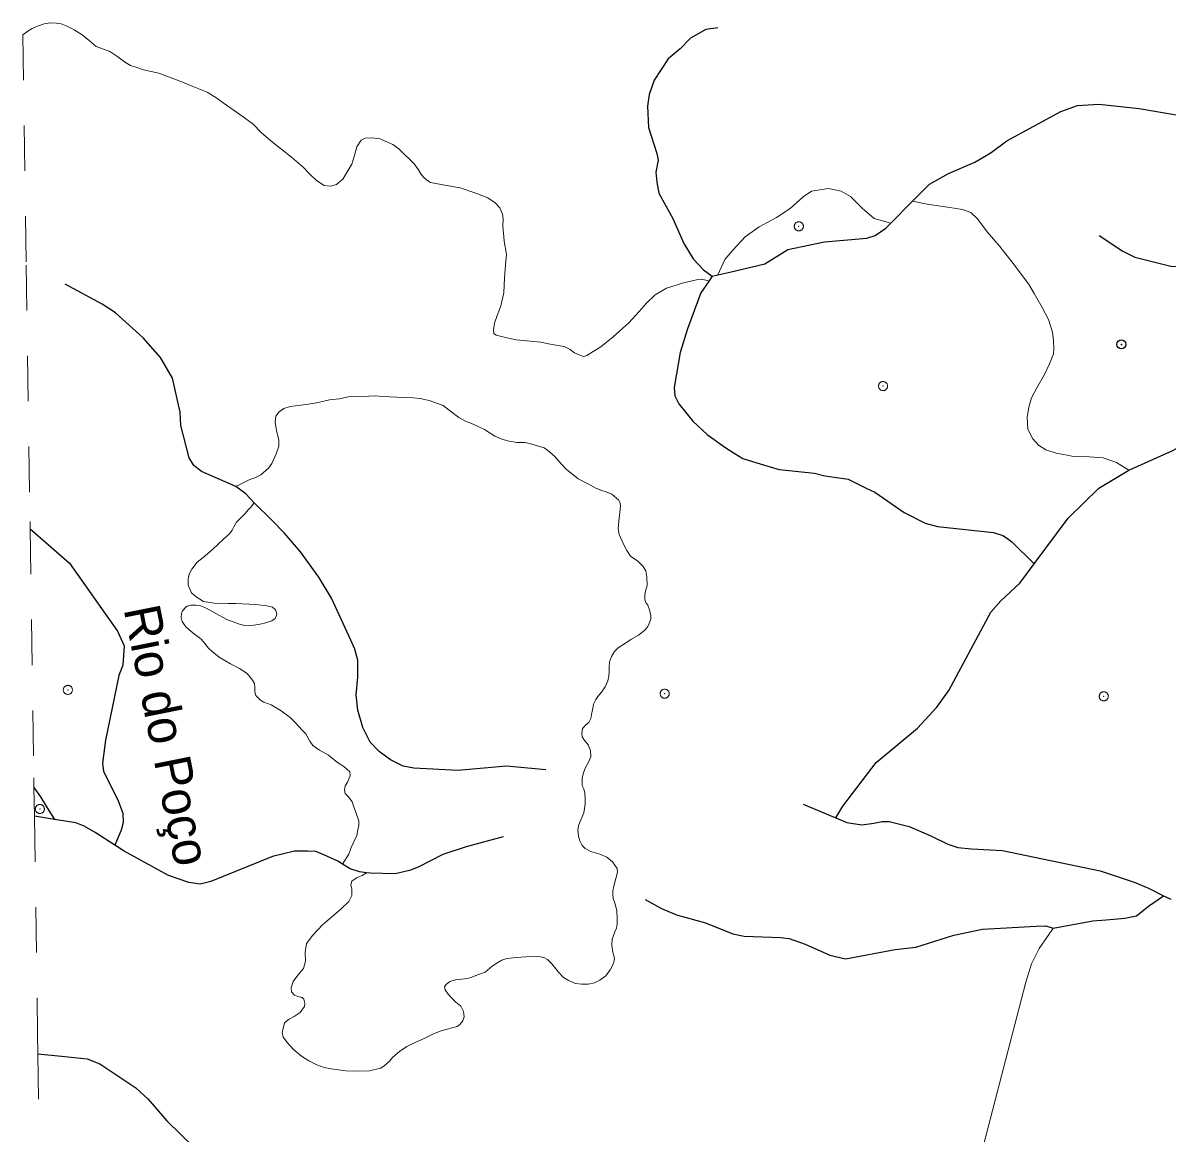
# Model space of a CAD drawing. Extents: x 267.7 to 296, y 7537.7 to 7565.8.
# Drawn here: x 267.776 to 270.298, y 7557.869 to 7560.316 of the extents above; entities that cross this region are included whole.
import ezdxf
from ezdxf.enums import TextEntityAlignment as Align

# ---------------------------------------------------------------- set-up
doc = ezdxf.new("R2010")
doc.units = 0
doc.header["$LTSCALE"] = 0.04
doc.header["$PDMODE"] = 32
doc.header["$PDSIZE"] = 0.02
doc.linetypes.add('SHORT_DASHED', pattern=[2.7, 1.5, -1.2])
for name, color, linetype, lineweight in [('1', 7, 'Continuous', 25), ('21', 7, 'SHORT_DASHED', 13), ('62', 7, 'SHORT_DASHED', 13), ('7', 7, 'Continuous', 25)]:
    doc.layers.add(name, color=color, linetype=linetype, lineweight=lineweight)
doc.layers.add('54', color=7, linetype='Continuous')
doc.layers.add('61', color=7, linetype='Continuous')

msp = doc.modelspace()

# ---------------------------------------------------------------- linework, layer by layer
at = {"layer": '1', "lineweight": 13}
msp.add_lwpolyline([(269.4313, 7557.2767), (269.5283, 7557.3725), (269.8469, 7557.6964), (269.8574, 7557.7104), (269.8653, 7557.7332), (269.8985, 7557.8627), (269.987, 7558.2015), (269.9992, 7558.2418), (270.0158, 7558.2759), (270.0342, 7558.3022), (270.0471, 7558.3206)], dxfattribs=at)
at = {"layer": '21'}
for points in [[(267.7967, 7560.3032), (267.7872, 7560.2972), (267.776, 7560.2894)], [(267.8606, 7560.3133), (267.8499, 7560.3151), (267.8361, 7560.3157), (267.823, 7560.3133), (267.8081, 7560.3085), (267.7967, 7560.3032)], [(269.2885, 7559.7474), (269.2712, 7559.7508), (269.261, 7559.7496), (269.2323, 7559.743), (269.1947, 7559.7311), (269.1696, 7559.7161), (269.1499, 7559.6976), (269.1344, 7559.6797), (269.1117, 7559.6546), (269.0771, 7559.6242), (269.0502, 7559.6021), (269.0329, 7559.5913), (269.0191, 7559.5824), (269.0126, 7559.5806), (269.0096, 7559.5812), (269.0018, 7559.5842), (268.9917, 7559.5889), (268.9821, 7559.5961), (268.969, 7559.6027), (268.9379, 7559.6075), (268.9176, 7559.6122), (268.8633, 7559.6176), (268.8424, 7559.6218), (268.8191, 7559.6278), (268.8143, 7559.6313), (268.8131, 7559.6391), (268.8155, 7559.654), (268.8215, 7559.6708), (268.8263, 7559.6839), (268.8292, 7559.6923), (268.8358, 7559.7209), (268.8376, 7559.7538), (268.84, 7559.7824), (268.8418, 7559.8051), (268.837, 7559.8344), (268.8358, 7559.8445), (268.834, 7559.8678), (268.8346, 7559.8828), (268.8334, 7559.8941), (268.8269, 7559.9084), (268.8167, 7559.9192), (268.8006, 7559.9299), (268.7743, 7559.9407), (268.7397, 7559.952), (268.7098, 7559.9574), (268.6746, 7559.964), (268.6662, 7559.9693), (268.6591, 7559.9759), (268.6531, 7559.9831), (268.6477, 7559.992), (268.6381, 7560.0052), (268.6292, 7560.0147), (268.6155, 7560.0273), (268.6053, 7560.0374), (268.5916, 7560.0476), (268.5748, 7560.0553), (268.5635, 7560.0601), (268.5462, 7560.0625), (268.5307, 7560.0619), (268.5217, 7560.0571), (268.5121, 7560.0422), (268.5074, 7560.0267), (268.5008, 7560.0046), (268.4811, 7559.9711), (268.4674, 7559.9592), (268.4542, 7559.9556), (268.4399, 7559.9574), (268.4232, 7559.9687), (268.4094, 7559.9819), (268.3939, 7559.998), (268.3682, 7560.0201), (268.3437, 7560.0392), (268.3228, 7560.0559), (268.3013, 7560.0744), (268.2834, 7560.0924), (268.2619, 7560.1085), (268.2177, 7560.1395), (268.2034, 7560.1497), (268.1825, 7560.1628), (268.1491, 7560.1766), (268.1168, 7560.1897), (268.0888, 7560.1999), (268.0756, 7560.2052), (268.0416, 7560.2124), (268.0272, 7560.2172), (268.0129, 7560.2219), (268.0022, 7560.2285), (267.9854, 7560.2411), (267.9675, 7560.2524), (267.9377, 7560.2638), (267.9221, 7560.2769), (267.9066, 7560.2894), (267.8887, 7560.3002), (267.8714, 7560.3091), (267.8606, 7560.3133)], [(269.308, 7559.7604), (269.323, 7559.7941), (269.3407, 7559.8148), (269.3683, 7559.8443), (269.3989, 7559.866), (269.4373, 7559.8867), (269.4669, 7559.9064), (269.4955, 7559.9321), (269.5142, 7559.9449), (269.5517, 7559.9508), (269.5793, 7559.9449), (269.6, 7559.933), (269.6256, 7559.9074), (269.6522, 7559.8848), (269.6889, 7559.8741)], [(269.7367, 7559.9225), (269.7695, 7559.9163), (269.8286, 7559.9074), (269.8473, 7559.9045), (269.8651, 7559.8976), (269.8799, 7559.8838), (269.9016, 7559.8552), (269.9292, 7559.8227), (269.9587, 7559.7852), (269.9922, 7559.7409), (270.005, 7559.7192), (270.0228, 7559.6886), (270.0366, 7559.662), (270.0455, 7559.6344), (270.0474, 7559.6157), (270.0484, 7559.5979), (270.0474, 7559.5861), (270.0386, 7559.5644), (270.0277, 7559.5408), (270.011, 7559.5112), (269.9991, 7559.4895), (269.9932, 7559.4688), (269.9893, 7559.4462), (269.9912, 7559.4205), (270.0021, 7559.3988), (270.0149, 7559.385), (270.0307, 7559.3752), (270.0533, 7559.3673), (270.078, 7559.3634), (270.0918, 7559.3604), (270.1263, 7559.3594), (270.1568, 7559.3574), (270.1864, 7559.3466), (270.2134, 7559.3302)], [(268.9248, 7559.3794), (268.8979, 7559.3872), (268.8829, 7559.3908), (268.8644, 7559.3908), (268.8477, 7559.3938), (268.8339, 7559.3974), (268.816, 7559.4052), (268.7932, 7559.4195), (268.7687, 7559.4315), (268.7514, 7559.4381), (268.737, 7559.4458), (268.7155, 7559.4626), (268.7023, 7559.4722), (268.6718, 7559.4835), (268.6515, 7559.4883), (268.6359, 7559.4895), (268.6162, 7559.4901), (268.5689, 7559.4925), (268.5534, 7559.4937), (268.5384, 7559.4931), (268.493, 7559.4913), (268.4738, 7559.4871), (268.4517, 7559.4847), (268.423, 7559.4787), (268.4002, 7559.4745), (268.365, 7559.4704), (268.3512, 7559.4656), (268.341, 7559.4584), (268.3338, 7559.4494), (268.3321, 7559.4357), (268.335, 7559.4171), (268.3404, 7559.3962), (268.3398, 7559.383), (268.3344, 7559.3663), (268.3249, 7559.3448), (268.3177, 7559.3346), (268.3004, 7559.3196), (268.2872, 7559.3131), (268.2764, 7559.3095), (268.2453, 7559.2937)], [(269.0002, 7559.3113), (268.9733, 7559.3322), (268.9625, 7559.3442), (268.9475, 7559.3609), (268.9332, 7559.3735), (268.9248, 7559.3794)], [(269.0857, 7558.3297), (269.0857, 7558.3405), (269.0851, 7558.3596), (269.0809, 7558.3758), (269.0767, 7558.3859), (269.0761, 7558.3955), (269.0761, 7558.4033), (269.0785, 7558.4134), (269.0833, 7558.4302), (269.0863, 7558.444), (269.0857, 7558.4523), (269.0755, 7558.4667), (269.063, 7558.4769), (269.048, 7558.484), (269.0379, 7558.487), (269.0277, 7558.49), (269.0151, 7558.496), (269.0091, 7558.5032), (269.0038, 7558.5133), (269.0008, 7558.5235), (268.999, 7558.5367), (269.0008, 7558.5468), (269.0068, 7558.5606), (269.0121, 7558.5749), (269.0151, 7558.5941), (269.0157, 7558.6055), (269.0145, 7558.6186), (269.0121, 7558.6276), (269.0091, 7558.6348), (269.0086, 7558.6443), (269.0086, 7558.6515), (269.0109, 7558.6605), (269.0157, 7558.6736), (269.0235, 7558.688), (269.0277, 7558.6982), (269.0271, 7558.7119), (269.0223, 7558.7245), (269.0127, 7558.7364), (269.0091, 7558.7424), (269.008, 7558.7496), (269.0097, 7558.7604), (269.0169, 7558.7687), (269.0235, 7558.7741), (269.0277, 7558.7825), (269.0295, 7558.7915), (269.0313, 7558.8022), (269.0325, 7558.8058), (269.0337, 7558.8142), (269.0391, 7558.825), (269.0432, 7558.8315), (269.051, 7558.8405), (269.0594, 7558.8525), (269.0654, 7558.8656), (269.0678, 7558.8758), (269.0684, 7558.8854), (269.0684, 7558.8961), (269.069, 7558.9075), (269.0732, 7558.9195), (269.0797, 7558.9302), (269.0881, 7558.9386), (269.1019, 7558.9476), (269.1162, 7558.9572), (269.133, 7558.9661), (269.1467, 7558.9775), (269.1533, 7558.9853), (269.1581, 7558.996), (269.1599, 7559.0026), (269.1599, 7559.0092), (269.1575, 7559.0224), (269.1533, 7559.0325), (269.1497, 7559.0373), (269.1467, 7559.0445), (269.1467, 7559.0553), (269.1485, 7559.0636), (269.1521, 7559.0762), (269.1515, 7559.0953), (269.1491, 7559.1085), (269.1431, 7559.1181), (269.1318, 7559.1294), (269.115, 7559.1408), (269.1072, 7559.1527), (269.0995, 7559.1671), (269.0905, 7559.1886), (269.0881, 7559.2006), (269.0893, 7559.2173), (269.0917, 7559.2371), (269.0929, 7559.252), (269.0917, 7559.2592), (269.0893, 7559.264), (269.0743, 7559.2772), (269.0618, 7559.2825), (269.0522, 7559.2855), (269.0385, 7559.2903), (269.0271, 7559.2969), (269.0002, 7559.3113)], [(268.2468, 7559.2152), (268.2561, 7559.2251), (268.2654, 7559.2338), (268.273, 7559.2432), (268.2783, 7559.2484), (268.2857, 7559.2581)], [(268.4806, 7558.4618), (268.4947, 7558.4841), (268.4994, 7558.4987), (268.5058, 7558.511), (268.5122, 7558.525), (268.5146, 7558.5372), (268.5163, 7558.5471), (268.5163, 7558.557), (268.5111, 7558.5716), (268.5064, 7558.5862), (268.5017, 7558.5991), (268.4936, 7558.6101), (268.4866, 7558.6177), (268.4848, 7558.6253), (268.486, 7558.6341), (268.4912, 7558.6428), (268.4976, 7558.6568), (268.4965, 7558.665), (268.4831, 7558.6767), (268.4691, 7558.686), (268.4574, 7558.6953), (268.4498, 7558.7017), (268.43, 7558.7128), (268.4154, 7558.7233), (268.4084, 7558.7327), (268.3996, 7558.749), (268.3915, 7558.7572), (268.3769, 7558.7735), (268.3652, 7558.7852), (268.3454, 7558.7998), (268.3232, 7558.8132), (268.3069, 7558.819), (268.2999, 7558.8231), (268.2894, 7558.8336), (268.2876, 7558.8412), (268.2876, 7558.8505), (268.2864, 7558.8599), (268.2824, 7558.8674), (268.2765, 7558.8744), (268.2701, 7558.882), (268.2538, 7558.8931), (268.2339, 7558.903), (268.2088, 7558.9182), (268.1931, 7558.9305), (268.1849, 7558.938), (268.1773, 7558.948), (268.1686, 7558.9579), (268.1546, 7558.9684), (268.1464, 7558.9754), (268.1359, 7558.9841), (268.1318, 7558.99), (268.1272, 7558.9964), (268.1248, 7559.0051), (268.1254, 7559.0145), (268.1277, 7559.0203), (268.1353, 7559.0279), (268.1382, 7559.0302), (268.1464, 7559.0326), (268.1581, 7559.0326), (268.1657, 7559.032), (268.1802, 7559.0261), (268.2024, 7559.0133), (268.2252, 7559.0011), (268.2532, 7558.9905), (268.2654, 7558.9876), (268.2847, 7558.9882), (268.2993, 7558.9905), (268.3115, 7558.9935), (268.3249, 7558.9981), (268.3319, 7559.0034), (268.3343, 7559.0081), (268.3354, 7559.0133), (268.3331, 7559.0221), (268.3261, 7559.0279), (268.3139, 7559.0314), (268.2894, 7559.0343), (268.245, 7559.0361), (268.2281, 7559.0361), (268.1978, 7559.0366), (268.1744, 7559.0407), (268.1581, 7559.0506), (268.1476, 7559.06), (268.1406, 7559.0769), (268.14, 7559.0915), (268.1429, 7559.102), (268.1482, 7559.1119), (268.1604, 7559.1271), (268.1732, 7559.1376), (268.1884, 7559.1504), (268.2048, 7559.1656), (268.2188, 7559.1784), (268.2316, 7559.1895), (268.2374, 7559.1977), (268.2409, 7559.2053), (268.2468, 7559.2152)], [(268.5335, 7558.443), (268.5235, 7558.4368), (268.5127, 7558.4326), (268.5013, 7558.4242), (268.4989, 7558.4164), (268.5013, 7558.4069), (268.5007, 7558.3925), (268.4947, 7558.3794), (268.4774, 7558.3632), (268.4559, 7558.3453), (268.4367, 7558.3279), (268.4152, 7558.3052), (268.4008, 7558.2872), (268.3984, 7558.2669), (268.399, 7558.2478), (268.3943, 7558.2316), (268.3823, 7558.2173), (268.3715, 7558.2029), (268.3673, 7558.1891), (268.3679, 7558.1808), (268.3745, 7558.173), (268.3823, 7558.17), (268.3919, 7558.1676), (268.3955, 7558.1646), (268.3978, 7558.1556), (268.3967, 7558.1479), (268.3871, 7558.1347), (268.3739, 7558.1263), (268.3626, 7558.1204), (268.353, 7558.112), (268.3476, 7558.091), (268.35, 7558.0803), (268.359, 7558.0677), (268.3721, 7558.054), (268.3901, 7558.039), (268.4062, 7558.0282), (268.4242, 7558.0199), (268.4403, 7558.0139), (268.4553, 7558.0109), (268.4876, 7558.0061), (268.5109, 7558.0055), (268.5402, 7558.0067), (268.5641, 7558.0121), (268.5713, 7558.0169), (268.5833, 7558.027), (268.5916, 7558.0366), (268.606, 7558.0486), (268.6222, 7558.0599), (268.6407, 7558.0689), (268.6616, 7558.0785), (268.6814, 7558.0881), (268.6981, 7558.0946), (268.7113, 7558.0982), (268.7334, 7558.1042), (268.7388, 7558.1084), (268.7454, 7558.1168), (268.7484, 7558.1257), (268.7472, 7558.1371), (268.7412, 7558.1485), (268.7304, 7558.1574), (268.7208, 7558.167), (268.7137, 7558.1754), (268.7065, 7558.185), (268.7053, 7558.1915), (268.7089, 7558.1963), (268.7167, 7558.2029), (268.7298, 7558.2071), (268.7561, 7558.2101), (268.7657, 7558.2131), (268.7777, 7558.2179), (268.795, 7558.2238), (268.8106, 7558.237), (268.8225, 7558.2454), (268.8315, 7558.2502), (268.8429, 7558.2537), (268.8638, 7558.2561), (268.8847, 7558.2579), (268.9128, 7558.2585), (268.9242, 7558.2561), (268.9326, 7558.2514), (268.9422, 7558.2424), (268.9565, 7558.2238), (268.9679, 7558.2119), (268.9786, 7558.2053), (268.9942, 7558.1987), (269.008, 7558.1975), (269.0217, 7558.1975), (269.0361, 7558.1999), (269.048, 7558.2059), (269.0606, 7558.2155), (269.0708, 7558.2292), (269.0779, 7558.243), (269.0797, 7558.2531), (269.0785, 7558.2603), (269.0761, 7558.2681)], [(269.0761, 7558.2681), (269.0743, 7558.2825), (269.0749, 7558.2968), (269.0809, 7558.3124), (269.0845, 7558.3207), (269.0857, 7558.3297)]]:
    msp.add_lwpolyline(points, dxfattribs=at)
for p in [(269.4863, 7559.8674), (269.672, 7559.5154), (267.8751, 7558.8459), (269.1906, 7558.8374), (270.1585, 7558.8317), (267.8134, 7558.5834)]:
    msp.add_point(p, dxfattribs=at)
at = {"layer": '54'}
msp.add_point((270.1974, 7559.6073), dxfattribs=at)
at = {"layer": '62'}
for points in [[(267.776, 7560.2894), (267.7835, 7559.7818), (267.7918, 7559.2168), (267.792, 7559.2006)], [(267.792, 7559.2006), (267.8001, 7558.6517), (267.8004, 7558.6309), (267.8014, 7558.5672)], [(267.8014, 7558.5672), (267.8085, 7558.0867), (267.8091, 7558.0441)], [(267.8091, 7558.0441), (267.8168, 7557.5216), (267.8197, 7557.3268)]]:
    msp.add_lwpolyline(points, dxfattribs=at)
at = {"layer": '7'}
for p, q in [((269.6889, 7559.8741), (269.7367, 7559.9225)), ((269.2953, 7559.7574), (269.2885, 7559.7474)), ((269.2953, 7559.7574), (269.308, 7559.7604)), ((270.2902, 7558.3919), (270.3059, 7558.3849))]:
    msp.add_line(p, q, dxfattribs=at)
for points in [[(269.3076, 7560.3047), (269.281, 7560.3008), (269.2477, 7560.2823), (269.2249, 7560.2583), (269.1984, 7560.2364), (269.1675, 7560.1898), (269.1562, 7560.1582), (269.1528, 7560.1324), (269.1546, 7560.0853), (269.1736, 7560.0282), (269.1764, 7560.0135), (269.1713, 7559.9868), (269.1736, 7559.9648), (269.1778, 7559.9401), (269.2087, 7559.8845), (269.2331, 7559.8294), (269.2535, 7559.7955), (269.2759, 7559.7712), (269.2952, 7559.7574), (269.2953, 7559.7574)], [(269.7367, 7559.9225), (269.7742, 7559.9605), (269.8159, 7559.9839), (269.8739, 7560.0089), (269.8955, 7560.0216), (269.91, 7560.0302), (269.9451, 7560.0557), (270.064, 7560.1203), (270.1005, 7560.1335), (270.1479, 7560.1368), (270.2362, 7560.1272), (270.3223, 7560.112)], [(269.308, 7559.7604), (269.3345, 7559.7667), (269.4115, 7559.785), (269.4622, 7559.8166), (269.5432, 7559.8333), (269.6363, 7559.8411), (269.6544, 7559.847), (269.6781, 7559.8632), (269.6889, 7559.8741)], [(270.1486, 7559.8475), (270.2006, 7559.8124), (270.2266, 7559.7993), (270.3065, 7559.7794), (270.3937, 7559.7769), (270.4703, 7559.7848), (270.5202, 7559.7809), (270.5366, 7559.7758), (270.5716, 7559.7648), (270.7117, 7559.686), (270.7752, 7559.6637), (270.8394, 7559.6643), (270.9422, 7559.6907), (271.0745, 7559.7046)], [(269.2885, 7559.7474), (269.2702, 7559.7207), (269.2406, 7559.6415), (269.2251, 7559.589), (269.2117, 7559.512), (269.2128, 7559.4941), (269.222, 7559.4761), (269.2523, 7559.4383), (269.2843, 7559.4089), (269.3232, 7559.3806), (269.3439, 7559.3676), (269.3632, 7559.3555), (269.4032, 7559.3432), (269.4432, 7559.3312), (269.5212, 7559.3235), (269.5433, 7559.3173), (269.5948, 7559.3103), (269.6349, 7559.2906), (269.6541, 7559.2812), (269.7187, 7559.2365), (269.7648, 7559.2133), (269.7916, 7559.2059), (269.9153, 7559.193), (269.9362, 7559.1863), (269.9459, 7559.1792), (269.9563, 7559.1717), (270.005, 7559.1234)], [(268.2453, 7559.2937), (268.1696, 7559.327), (268.1529, 7559.3406), (268.1423, 7559.3569), (268.1243, 7559.4288), (268.1229, 7559.4575), (268.1055, 7559.5327), (268.079, 7559.5785), (268.041, 7559.6214), (267.9804, 7559.6766), (267.951, 7559.6958), (267.8689, 7559.7398)], [(270.2134, 7559.3302), (270.3107, 7559.3734), (270.3778, 7559.4119), (270.4286, 7559.4347), (270.5024, 7559.4597), (270.5697, 7559.4745), (270.6231, 7559.4731), (270.6396, 7559.4713), (270.9292, 7559.4407)], [(270.005, 7559.1234), (270.0797, 7559.2241), (270.1477, 7559.2902), (270.2134, 7559.3302)], [(268.2857, 7559.2581), (268.2671, 7559.2782), (268.2453, 7559.2937)], [(268.9286, 7558.6698), (268.8422, 7558.6775), (268.7347, 7558.6681), (268.6375, 7558.673), (268.6139, 7558.6781), (268.5862, 7558.6914), (268.5616, 7558.7099), (268.5413, 7558.7305), (268.5252, 7558.7629), (268.5143, 7558.8013), (268.5107, 7558.835), (268.5143, 7558.8741), (268.5143, 7558.9111), (268.5074, 7558.9356), (268.4988, 7558.9555), (268.4564, 7559.0478), (268.428, 7559.0939), (268.388, 7559.1504), (268.3528, 7559.1913), (268.3249, 7559.2198), (268.2857, 7559.2581)], [(267.792, 7559.2006), (267.8784, 7559.1252), (267.9843, 7558.9754), (267.9994, 7558.9426), (267.9964, 7558.9004), (267.9873, 7558.8778), (267.9579, 7558.7348), (267.9516, 7558.684), (267.9534, 7558.6659), (267.985, 7558.6038), (267.996, 7558.5744), (267.997, 7558.5539), (267.9929, 7558.5364), (267.9785, 7558.5035)], [(269.568, 7558.5638), (269.5831, 7558.5899), (269.6568, 7558.6856), (269.7479, 7558.7616), (269.7906, 7558.8078), (269.8166, 7558.8445), (269.9095, 7559.0171), (269.9314, 7559.042), (269.9736, 7559.0811), (270.005, 7559.1234)], [(267.8004, 7558.6309), (267.8145, 7558.6104), (267.8295, 7558.5858), (267.846, 7558.56)], [(269.4958, 7558.5943), (269.5552, 7558.5692), (269.568, 7558.5638)], [(267.846, 7558.56), (267.841, 7558.5608), (267.8014, 7558.5672)], [(267.9785, 7558.5035), (267.9356, 7558.5314), (267.9108, 7558.5457), (267.8928, 7558.5525), (267.846, 7558.56)], [(269.568, 7558.5638), (269.5922, 7558.5536), (269.6251, 7558.5488), (269.6516, 7558.5518), (269.6701, 7558.5559), (269.6855, 7558.5559), (269.7296, 7558.5447), (269.7776, 7558.5244), (269.8148, 7558.5057), (269.8364, 7558.4985), (269.8672, 7558.4954), (269.9349, 7558.4918), (270.1503, 7558.4474), (270.2257, 7558.4221), (270.2572, 7558.4092), (270.2902, 7558.3919)], [(268.8348, 7558.5221), (268.7528, 7558.4997), (268.7018, 7558.4829), (268.6476, 7558.4549), (268.6284, 7558.4478), (268.5963, 7558.4402), (268.5414, 7558.4421), (268.5335, 7558.443)], [(268.4806, 7558.4618), (268.4704, 7558.4682), (268.4391, 7558.4827), (268.4218, 7558.4894), (268.4037, 7558.4905), (268.3745, 7558.4905), (268.3259, 7558.479), (268.1904, 7558.4235), (268.1664, 7558.4174), (268.1418, 7558.4215), (268.0966, 7558.4369), (267.999, 7558.4901), (267.9785, 7558.5035)], [(268.5335, 7558.443), (268.5181, 7558.4448), (268.4971, 7558.4514), (268.4806, 7558.4618)], [(269.1475, 7558.3838), (269.1836, 7558.364), (269.2167, 7558.35), (269.2806, 7558.3328), (269.3408, 7558.3083), (269.3659, 7558.3028), (269.4461, 7558.2999), (269.4648, 7558.2983), (269.5004, 7558.2858), (269.5545, 7558.2616), (269.5892, 7558.2534), (269.6988, 7558.2737), (269.744, 7558.2787), (269.828, 7558.3052), (269.8913, 7558.3183), (270.0093, 7558.3253), (270.0304, 7558.326), (270.0471, 7558.3206)], [(270.0471, 7558.3206), (270.1345, 7558.3367), (270.1638, 7558.3394), (270.2048, 7558.3425), (270.2305, 7558.3476), (270.2572, 7558.3691), (270.2902, 7558.3919)], [(267.8091, 7558.0441), (267.8608, 7558.0389), (267.9179, 7558.0331), (267.9458, 7558.022), (268.0251, 7557.9692), (268.0522, 7557.9439), (268.093, 7557.896), (268.1844, 7557.8074)]]:
    msp.add_lwpolyline(points, dxfattribs=at)

# ---------------------------------------------------------------- texts
at = {"layer": '61'}
msp.add_text('Rio do Poço', height=0.08, rotation=281.31, dxfattribs=at).set_placement((268.055, 7558.7383), align=Align.CENTER)

doc.saveas('drawing.dxf')
